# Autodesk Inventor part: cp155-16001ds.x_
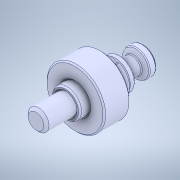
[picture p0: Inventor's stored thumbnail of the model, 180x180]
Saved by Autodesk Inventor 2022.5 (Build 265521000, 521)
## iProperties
Created: 2023-04
Part Number: cp155-16001ds.x_
Material: Generic
Document SubType Name: Modeling
Designer: ImaoCorp
Density: 1 g/cm^3
Appearance: Default
Sending System: SOLIDWORKS 2021-2021301
MC: AMD64
MC_MODEL: Intel64 Family 6 Model 60 Stepping 3, GenuineIntel
OS: Windows_NT
FRU: Parasolid Version 32.1, build 255,  1- 1-2021
FORMAT: text
GUISE: transmit
KEY: cp155-16001ds
FILE: cp155-16001ds.x_t
DATE: Fri Apr  7 10:53:30 2023
Author: ImaoCorp
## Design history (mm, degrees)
feature "Base1"
node "ソリッド1"
